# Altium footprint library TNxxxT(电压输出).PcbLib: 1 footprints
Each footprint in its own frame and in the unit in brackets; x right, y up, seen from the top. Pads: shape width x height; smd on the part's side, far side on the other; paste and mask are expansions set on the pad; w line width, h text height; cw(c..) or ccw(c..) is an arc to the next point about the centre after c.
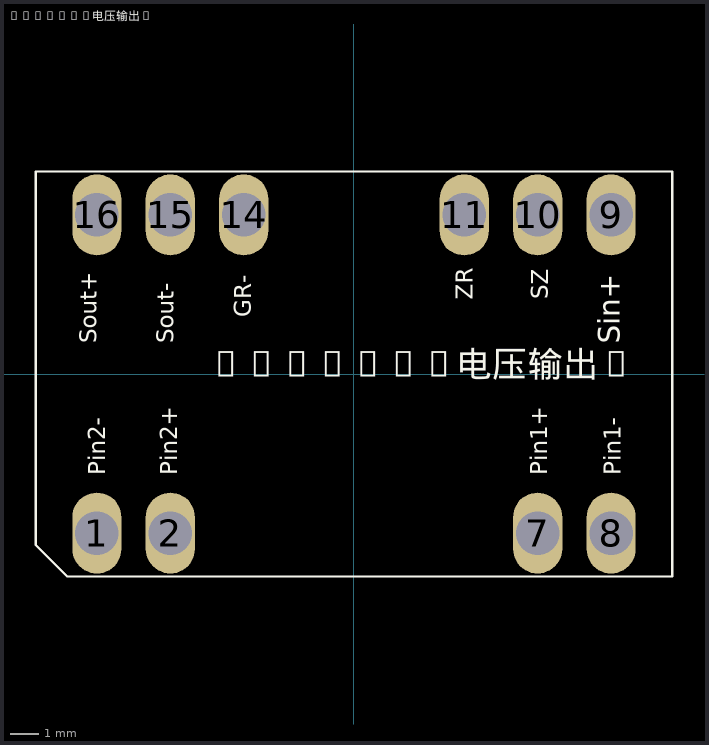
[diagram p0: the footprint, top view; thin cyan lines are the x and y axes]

## TNxxxT(电压输出) [mm]
pads (10):
  oval 1.7x2.8 hole 1.5 mask+0.102: 1(-8.89,-5.5) 2(-6.35,-5.5) 7(6.35,-5.5) 8(8.89,-5.5) 9(8.89,5.5) 10(6.35,5.5) 11(3.81,5.5) 14(-3.81,5.5) 15(-6.35,5.5) 16(-8.89,5.5)
Top Overlay:
  lines w0.076: -11,-5.909 -9.909,-7 11,-7 11,7 -11,7 -11,-5.909
  text "Sout+" at -8.712,1.064 h1
  text "Sout-" at -6.048,1.068 h1
  text "GR-" at -3.368,1.962 h1
  text "ZR" at 4.299,2.562 h1
  text "SZ" at 6.914,2.577 h1
  text "Sin+" at 9.432,1.043 h1.27
  text "TNxxxT(电压输出)" at -5.037,-0.393 h1.52
  text "Pin2-" at -8.405,-3.494 h1
  text "Pin2+" at -5.922,-3.494 h1
  text "Pin1+" at 6.878,-3.494 h1
  text "Pin1-" at 9.418,-3.494 h1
